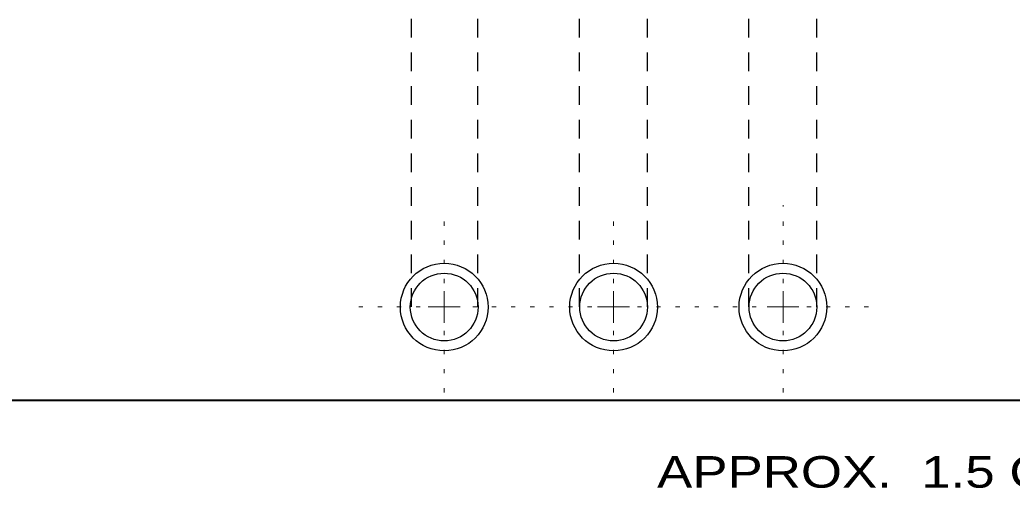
# Model space of a CAD drawing. Extents: x 312583 to 312854, y 144419 to 144597.
# Drawn here: x 312766.33 to 312790.2, y 144440.37 to 144451.63 of the extents above; entities that cross this region are included whole.
import ezdxf

# ---------------------------------------------------------------- set-up
doc = ezdxf.new("R2010")
doc.units = 0
doc.header["$LTSCALE"] = 0.3
doc.linetypes.add('DOTTED', pattern=[1.5, 0.3, -1.2])
doc.linetypes.add('SHORT_DASHED', pattern=[2.7, 1.5, -1.2])
doc.layers.add('1', color=7, linetype='Continuous', lineweight=25)
doc.layers.add('2', color=7, linetype='Continuous', lineweight=13)

msp = doc.modelspace()

# ---------------------------------------------------------------- linework, layer by layer
at = {"layer": '1', "linetype": 'SHORT_DASHED'}
for p, q in [((312775.7536, 144444.7255), (312775.7536, 144456.0645)), ((312777.3482, 144444.7255), (312777.3482, 144456.0645)), ((312779.7939, 144444.7255), (312779.7939, 144456.0645)), ((312781.4269, 144444.7255), (312781.4269, 144456.0645)), ((312783.8649, 144444.7255), (312783.8649, 144456.0645)), ((312785.4979, 144444.7255), (312785.4979, 144456.0645))]:
    msp.add_line(p, q, dxfattribs=at)
at = {"layer": '1', "lineweight": 40}
msp.add_line((312728.2202, 144442.4868), (312794.6672, 144442.4868), dxfattribs=at)
at = {"layer": '1'}
for centre, radius in [((312776.5362, 144444.7235), 1.0542), ((312780.6091, 144444.7235), 1.0542), ((312784.682, 144444.7235), 1.0542), ((312776.5362, 144444.7235), 0.8146), ((312780.6091, 144444.7235), 0.8146), ((312784.682, 144444.7235), 0.8146)]:
    msp.add_circle(centre, radius, dxfattribs=at)
at = {"layer": '2', "linetype": 'DOTTED'}
for p, q in [((312784.6852, 144445.3005), (312784.6852, 144447.1711)), ((312776.5356, 144445.3005), (312776.5356, 144447.0561)), ((312780.6066, 144445.3005), (312780.6066, 144447.1021)), ((312775.9606, 144444.7255), (312774.1512, 144444.7255)), ((312780.0852, 144444.7255), (312777.0646, 144444.7255)), ((312781.1816, 144444.7255), (312784.1486, 144444.7255)), ((312785.2602, 144444.7255), (312786.9086, 144444.7255)), ((312776.5356, 144444.1505), (312776.5356, 144442.5328)), ((312780.6066, 144444.1505), (312780.6066, 144442.5021)), ((312784.6852, 144444.1505), (312784.6852, 144442.5711))]:
    msp.add_line(p, q, dxfattribs=at)
at = {"layer": '2'}
for p, q in [((312776.5356, 144444.7255), (312776.5356, 144445.1088)), ((312780.6066, 144444.7255), (312780.6066, 144445.1088)), ((312784.6852, 144444.7255), (312784.6852, 144445.1088)), ((312776.5356, 144444.7255), (312776.1522, 144444.7255)), ((312776.5356, 144444.7255), (312776.9189, 144444.7255)), ((312776.5356, 144444.7255), (312776.5356, 144444.3421)), ((312780.6066, 144444.7255), (312780.2232, 144444.7255)), ((312780.6066, 144444.7255), (312780.9899, 144444.7255)), ((312780.6066, 144444.7255), (312780.6066, 144444.3421)), ((312784.6852, 144444.7255), (312784.3019, 144444.7255)), ((312784.6852, 144444.7255), (312785.0686, 144444.7255)), ((312784.6852, 144444.7255), (312784.6852, 144444.3421))]:
    msp.add_line(p, q, dxfattribs=at)

# ---------------------------------------------------------------- texts
at = {"layer": '2', "width": 1.25}
msp.add_text('APPROX.  1.5 C.M.', height=0.76, dxfattribs=at).set_placement((312781.6558, 144440.3775))

doc.saveas('drawing.dxf')
